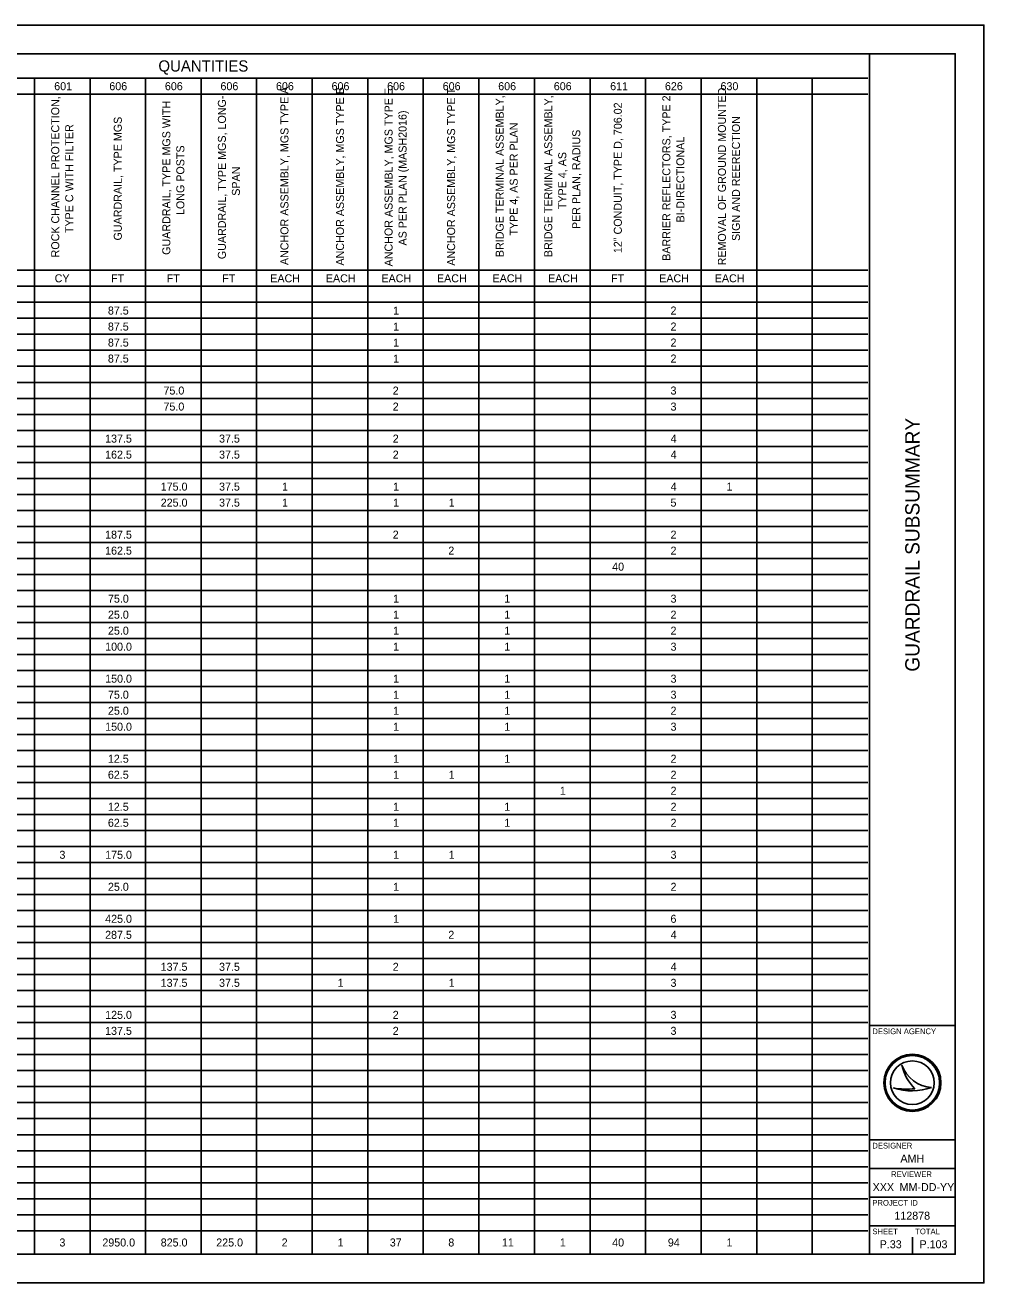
# Model space of a CAD drawing. Extents: x 0 to 34, y 0 to 22.
# Drawn here: x 17.23 to 34, y 0 to 22 of the extents above; entities that cross this region are included whole.
import ezdxf

# ---------------------------------------------------------------- set-up
doc = ezdxf.new("R2010")
doc.units = 0
for name, color, linetype in [('Default', 7, 'Continuous'), ('SH_Border', 7, 'Continuous'), ('SH_Cut_Line', 7, 'Continuous'), ('SH_Data', 7, 'Continuous')]:
    doc.layers.add(name, color=color, linetype=linetype)

msp = doc.modelspace()

# ---------------------------------------------------------------- linework, layer by layer
at = {"layer": 'Default'}
for p, q in [((1.5, 21.072), (31.971, 21.072)), ((17.394, 21.072), (17.394, 0.5)), ((18.366, 21.072), (18.366, 0.5)), ((19.338, 21.072), (19.338, 0.5)), ((20.309, 21.072), (20.309, 0.5)), ((21.281, 21.072), (21.281, 0.5)), ((22.253, 21.072), (22.253, 0.5)), ((23.225, 21.072), (23.225, 0.5)), ((24.196, 21.072), (24.196, 0.5)), ((25.168, 21.072), (25.168, 0.5)), ((26.14, 21.072), (26.14, 0.5)), ((27.112, 21.072), (27.112, 0.5)), ((28.084, 21.072), (28.084, 0.5)), ((29.055, 21.072), (29.055, 0.5)), ((30.027, 21.072), (30.027, 0.5)), ((30.999, 21.072), (30.999, 0.5)), ((8.648, 20.792), (31.971, 20.792)), ((8.648, 17.712), (31.971, 17.712)), ((1.5, 17.432), (31.971, 17.432)), ((1.5, 17.152), (31.971, 17.152)), ((1.5, 16.872), (31.971, 16.872)), ((1.5, 16.592), (31.971, 16.592)), ((1.5, 16.312), (31.971, 16.312)), ((1.5, 16.032), (31.971, 16.032)), ((1.5, 15.752), (31.971, 15.752)), ((1.5, 15.472), (31.971, 15.472)), ((1.5, 15.192), (31.971, 15.192)), ((1.5, 14.912), (31.971, 14.912)), ((1.5, 14.632), (31.971, 14.632)), ((1.5, 14.352), (31.971, 14.352)), ((1.5, 14.072), (31.971, 14.072)), ((1.5, 13.792), (31.971, 13.792)), ((1.5, 13.512), (31.971, 13.512)), ((1.5, 13.232), (31.971, 13.232)), ((1.5, 12.952), (31.971, 12.952)), ((1.5, 12.672), (31.971, 12.672)), ((1.5, 12.392), (31.971, 12.392)), ((1.5, 12.112), (31.971, 12.112)), ((1.5, 11.832), (31.971, 11.832)), ((1.5, 11.552), (31.971, 11.552)), ((1.5, 11.272), (31.971, 11.272)), ((1.5, 10.992), (31.971, 10.992)), ((1.5, 10.712), (31.971, 10.712)), ((1.5, 10.432), (31.971, 10.432)), ((1.5, 10.152), (31.971, 10.152)), ((1.5, 9.872), (31.971, 9.872)), ((1.5, 9.592), (31.971, 9.592)), ((1.5, 9.312), (31.971, 9.312)), ((1.5, 9.032), (31.971, 9.032)), ((1.5, 8.752), (31.971, 8.752)), ((1.5, 8.472), (31.971, 8.472)), ((1.5, 8.192), (31.971, 8.192)), ((1.5, 7.912), (31.971, 7.912)), ((1.5, 7.632), (31.971, 7.632)), ((1.5, 7.352), (31.971, 7.352)), ((1.5, 7.072), (31.971, 7.072)), ((1.5, 6.792), (31.971, 6.792)), ((1.5, 6.512), (31.971, 6.512)), ((1.5, 6.232), (31.971, 6.232)), ((1.5, 5.952), (31.971, 5.952)), ((1.5, 5.672), (31.971, 5.672)), ((1.5, 5.392), (31.971, 5.392)), ((1.5, 5.112), (31.971, 5.112)), ((1.5, 4.832), (31.971, 4.832)), ((1.5, 4.552), (31.971, 4.552)), ((1.5, 4.272), (31.971, 4.272)), ((1.5, 3.992), (31.971, 3.992)), ((1.5, 3.712), (31.971, 3.712)), ((1.5, 3.432), (31.971, 3.432)), ((1.5, 3.152), (31.971, 3.152)), ((1.5, 2.872), (31.971, 2.872)), ((1.5, 2.592), (31.971, 2.592)), ((1.5, 2.312), (31.971, 2.312)), ((1.5, 2.032), (31.971, 2.032)), ((1.5, 1.752), (31.971, 1.752)), ((1.5, 1.472), (31.971, 1.472)), ((1.5, 1.192), (31.971, 1.192)), ((1.5, 0.912), (31.971, 0.912))]:
    msp.add_line(p, q, dxfattribs=at)
at = {"layer": 'SH_Border'}
for p, q in [((32, 0.5), (32, 21.5)), ((32, 4.5), (33.5, 4.5)), ((32, 2.5), (33.5, 2.5)), ((32, 2), (33.5, 2)), ((32, 1.5), (33.5, 1.5)), ((32, 1), (33.5, 1))]:
    msp.add_line(p, q, dxfattribs=at)
msp.add_lwpolyline([(1.5, 21.5), (33.5, 21.5), (33.5, 0.5), (1.5, 0.5)], close=True, dxfattribs=at)
at = {"layer": 'SH_Cut_Line'}
msp.add_lwpolyline([(0, 0), (34, 0), (34, 22), (0, 22)], close=True, dxfattribs=at)
at = {"layer": 'SH_Data'}
for p, q in [((32.567, 3.81), (32.567, 3.81)), ((32.417, 3.41), (32.417, 3.41)), ((32.75, 3.5), (32.75, 3.5)), ((33.087, 3.419), (33.087, 3.419)), ((32.375, 0.675), (32.375, 0.675)), ((32.75, 0.5), (32.75, 0.8))]:
    msp.add_line(p, q, dxfattribs=at)
for radius in [0.5, 0.477, 0.477, 0.382]:
    msp.add_circle((32.75, 3.5), radius, dxfattribs=at)
for centre, radius, start, end in [((33.116, 3.998), 0.58, 198.9257, 198.9319), ((33.347, 3.97), 0.796, 191.6379, 191.6421), ((33.116, 3.998), 0.58, 198.9319, 267.1657), ((33.347, 3.97), 0.796, 191.6421, 226.0947), ((32.739, 4.37), 1.013, 251.4576, 290.0832), ((32.648, 4.654), 1.266, 259.4964, 259.4995), ((32.739, 4.37), 1.013, 251.4527, 251.4576), ((32.648, 4.654), 1.266, 259.4995, 276.6672)]:
    msp.add_arc(centre, radius, start, end, dxfattribs=at)

# ---------------------------------------------------------------- texts
at = {"layer": 'Default'}
for s, height, p in [('QUANTITIES', 0.196, (19.562, 21.188)), ('601', 0.14, (17.74, 20.862)), ('606', 0.14, (18.704, 20.862)), ('606', 0.14, (19.676, 20.862)), ('606', 0.14, (20.648, 20.862)), ('606', 0.14, (21.619, 20.862)), ('606', 0.14, (22.591, 20.862)), ('606', 0.14, (23.563, 20.862)), ('606', 0.14, (24.535, 20.862)), ('606', 0.14, (25.506, 20.862)), ('606', 0.14, (26.478, 20.862)), ('611', 0.14, (27.464, 20.862)), ('626', 0.14, (28.422, 20.862)), ('630', 0.14, (29.394, 20.862)), ('CY', 0.14, (17.748, 17.502)), ('FT', 0.14, (18.736, 17.502)), ('FT', 0.14, (19.707, 17.502)), ('FT', 0.14, (20.679, 17.502)), ('EACH', 0.14, (21.519, 17.502)), ('EACH', 0.14, (22.491, 17.502)), ('EACH', 0.14, (23.463, 17.502)), ('EACH', 0.14, (24.435, 17.502)), ('EACH', 0.14, (25.407, 17.502)), ('EACH', 0.14, (26.378, 17.502)), ('FT', 0.14, (27.481, 17.502)), ('EACH', 0.14, (28.322, 17.502)), ('EACH', 0.14, (29.294, 17.502)), ('87.5', 0.14, (18.679, 16.938)), ('1', 0.14, (23.668, 16.938)), ('2', 0.14, (28.52, 16.938)), ('87.5', 0.14, (18.679, 16.658)), ('1', 0.14, (23.668, 16.658)), ('2', 0.14, (28.52, 16.658)), ('87.5', 0.14, (18.679, 16.378)), ('1', 0.14, (23.668, 16.378)), ('2', 0.14, (28.52, 16.378)), ('87.5', 0.14, (18.679, 16.098)), ('1', 0.14, (23.668, 16.098)), ('2', 0.14, (28.52, 16.098)), ('75.0', 0.14, (19.651, 15.538)), ('2', 0.14, (23.661, 15.538)), ('3', 0.14, (28.52, 15.538)), ('75.0', 0.14, (19.651, 15.258)), ('2', 0.14, (23.661, 15.258)), ('3', 0.14, (28.52, 15.258)), ('137.5', 0.14, (18.63, 14.698)), ('37.5', 0.14, (20.623, 14.698)), ('2', 0.14, (23.661, 14.698)), ('4', 0.14, (28.522, 14.698)), ('162.5', 0.14, (18.63, 14.418)), ('37.5', 0.14, (20.623, 14.418)), ('2', 0.14, (23.661, 14.418)), ('4', 0.14, (28.522, 14.418)), ('175.0', 0.14, (19.603, 13.858)), ('37.5', 0.14, (20.623, 13.858)), ('1', 0.14, (21.725, 13.858)), ('1', 0.14, (23.668, 13.858)), ('4', 0.14, (28.522, 13.858)), ('1', 0.14, (29.499, 13.858)), ('225.0', 0.14, (19.603, 13.578)), ('37.5', 0.14, (20.623, 13.578)), ('1', 0.14, (21.725, 13.578)), ('1', 0.14, (23.668, 13.578)), ('1', 0.14, (24.64, 13.578)), ('5', 0.14, (28.519, 13.578)), ('187.5', 0.14, (18.63, 13.018)), ('2', 0.14, (23.661, 13.018)), ('2', 0.14, (28.52, 13.018)), ('162.5', 0.14, (18.63, 12.738)), ('2', 0.14, (24.633, 12.738)), ('2', 0.14, (28.52, 12.738)), ('40', 0.14, (27.499, 12.458)), ('75.0', 0.14, (18.68, 11.898)), ('1', 0.14, (23.668, 11.898)), ('1', 0.14, (25.612, 11.898)), ('3', 0.14, (28.52, 11.898)), ('25.0', 0.14, (18.68, 11.618)), ('1', 0.14, (23.668, 11.618)), ('1', 0.14, (25.612, 11.618)), ('2', 0.14, (28.52, 11.618)), ('25.0', 0.14, (18.68, 11.338)), ('1', 0.14, (23.668, 11.338)), ('1', 0.14, (25.612, 11.338)), ('2', 0.14, (28.52, 11.338)), ('100.0', 0.14, (18.631, 11.058)), ('1', 0.14, (23.668, 11.058)), ('1', 0.14, (25.612, 11.058)), ('3', 0.14, (28.52, 11.058)), ('150.0', 0.14, (18.631, 10.498)), ('1', 0.14, (23.668, 10.498)), ('1', 0.14, (25.612, 10.498)), ('3', 0.14, (28.52, 10.498)), ('75.0', 0.14, (18.68, 10.218)), ('1', 0.14, (23.668, 10.218)), ('1', 0.14, (25.612, 10.218)), ('3', 0.14, (28.52, 10.218)), ('25.0', 0.14, (18.68, 9.938)), ('1', 0.14, (23.668, 9.938)), ('1', 0.14, (25.612, 9.938)), ('2', 0.14, (28.52, 9.938)), ('150.0', 0.14, (18.631, 9.658)), ('1', 0.14, (23.668, 9.658)), ('1', 0.14, (25.612, 9.658)), ('3', 0.14, (28.52, 9.658)), ('12.5', 0.14, (18.679, 9.098)), ('1', 0.14, (23.668, 9.098)), ('1', 0.14, (25.612, 9.098)), ('2', 0.14, (28.52, 9.098)), ('62.5', 0.14, (18.679, 8.818)), ('1', 0.14, (23.668, 8.818)), ('1', 0.14, (24.64, 8.818)), ('2', 0.14, (28.52, 8.818)), ('1', 0.14, (26.584, 8.538)), ('2', 0.14, (28.52, 8.538)), ('12.5', 0.14, (18.679, 8.258)), ('1', 0.14, (23.668, 8.258)), ('1', 0.14, (25.612, 8.258)), ('2', 0.14, (28.52, 8.258)), ('62.5', 0.14, (18.679, 7.978)), ('1', 0.14, (23.668, 7.978)), ('1', 0.14, (25.612, 7.978)), ('2', 0.14, (28.52, 7.978)), ('3', 0.14, (17.831, 7.418)), ('175.0', 0.14, (18.631, 7.418)), ('1', 0.14, (23.668, 7.418)), ('1', 0.14, (24.64, 7.418)), ('3', 0.14, (28.52, 7.418)), ('25.0', 0.14, (18.68, 6.858)), ('1', 0.14, (23.668, 6.858)), ('2', 0.14, (28.52, 6.858)), ('425.0', 0.14, (18.631, 6.298)), ('1', 0.14, (23.668, 6.298)), ('6', 0.14, (28.519, 6.298)), ('287.5', 0.14, (18.63, 6.018)), ('2', 0.14, (24.633, 6.018)), ('4', 0.14, (28.522, 6.018)), ('137.5', 0.14, (19.602, 5.458)), ('37.5', 0.14, (20.623, 5.458)), ('2', 0.14, (23.661, 5.458)), ('4', 0.14, (28.522, 5.458)), ('137.5', 0.14, (19.602, 5.178)), ('37.5', 0.14, (20.623, 5.178)), ('1', 0.14, (22.697, 5.178)), ('1', 0.14, (24.64, 5.178)), ('3', 0.14, (28.52, 5.178)), ('125.0', 0.14, (18.631, 4.618)), ('2', 0.14, (23.661, 4.618)), ('3', 0.14, (28.52, 4.618)), ('137.5', 0.14, (18.63, 4.338)), ('2', 0.14, (23.661, 4.338)), ('3', 0.14, (28.52, 4.338)), ('3', 0.14, (17.831, 0.636)), ('2950.0', 0.14, (18.582, 0.636)), ('825.0', 0.14, (19.603, 0.636)), ('225.0', 0.14, (20.574, 0.636)), ('2', 0.14, (21.718, 0.636)), ('1', 0.14, (22.697, 0.636)), ('37', 0.14, (23.609, 0.636)), ('8', 0.14, (24.633, 0.636)), ('11', 0.14, (25.57, 0.636)), ('1', 0.14, (26.584, 0.636)), ('40', 0.14, (27.499, 0.636)), ('94', 0.14, (28.473, 0.636)), ('1', 0.14, (29.499, 0.636))]:
    msp.add_text(s, height=height, dxfattribs=at).set_placement(p)
for s, p in [('ANCHOR ASSEMBLY, MGS TYPE A', (21.837, 17.803)), ('ANCHOR ASSEMBLY, MGS TYPE B', (22.809, 17.795)), ('ANCHOR ASSEMBLY, MGS TYPE E, ', (23.658, 17.78)), ('ROCK CHANNEL PROTECTION, ', (17.828, 17.937)), ('GUARDRAIL, TYPE MGS, LONG-', (20.743, 17.907)), ('ANCHOR ASSEMBLY, MGS TYPE T', (24.752, 17.792)), ('BRIDGE TERMINAL ASSEMBLY, ', (25.602, 17.943)), ('BRIDGE TERMINAL ASSEMBLY, ', (26.451, 17.943)), ('BARRIER REFLECTORS, TYPE 2, ', (28.517, 17.878)), ('REMOVAL OF GROUND MOUNTED ', (29.489, 17.798)), ('GUARDRAIL, TYPE MGS WITH ', (19.771, 17.982)), ('AS PER PLAN (MASH2016)', (23.903, 18.146)), ('12" CONDUIT, TYPE D, 706.02', (27.668, 18.012)), ('TYPE C WITH FILTER', (18.073, 18.363)), ('GUARDRAIL, TYPE MGS', (18.922, 18.234)), ('TYPE 4, AS PER PLAN', (25.847, 18.319)), ('SIGN AND REERECTION', (29.734, 18.225)), ('PER PLAN, RADIUS', (26.941, 18.434)), ('BI-DIRECTIONAL', (28.762, 18.55)), ('LONG POSTS', (20.016, 18.679)), ('TYPE 4, AS ', (26.696, 18.782)), ('SPAN', (20.988, 19.016))]:
    msp.add_text(s, height=0.14, rotation=90, dxfattribs=at).set_placement(p)
at = {"layer": 'SH_Data'}
msp.add_text('GUARDRAIL SUBSUMMARY', height=0.25, rotation=90, dxfattribs=at).set_placement((32.875, 10.691))
for s, height, p in [('DESIGN AGENCY', 0.1, (32.05, 4.35)), ('DESIGNER', 0.1, (32.05, 2.35)), ('AMH', 0.14, (32.541, 2.105)), ('REVIEWER', 0.1, (32.378, 1.85)), ('XXX', 0.14, (32.055, 1.605)), ('MM-DD-YY', 0.14, (32.526, 1.605)), ('PROJECT ID', 0.1, (32.05, 1.35)), ('112878', 0.14, (32.435, 1.105)), ('SHEET', 0.1, (32.05, 0.85)), ('TOTAL', 0.1, (32.8, 0.85)), ('P.33', 0.14, (32.178, 0.605)), ('P.103', 0.14, (32.874, 0.605))]:
    msp.add_text(s, height=height, dxfattribs=at).set_placement(p)

doc.saveas('drawing.dxf')
